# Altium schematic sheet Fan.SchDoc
size A4; SheetNumber: 9; SheetTotal: 16
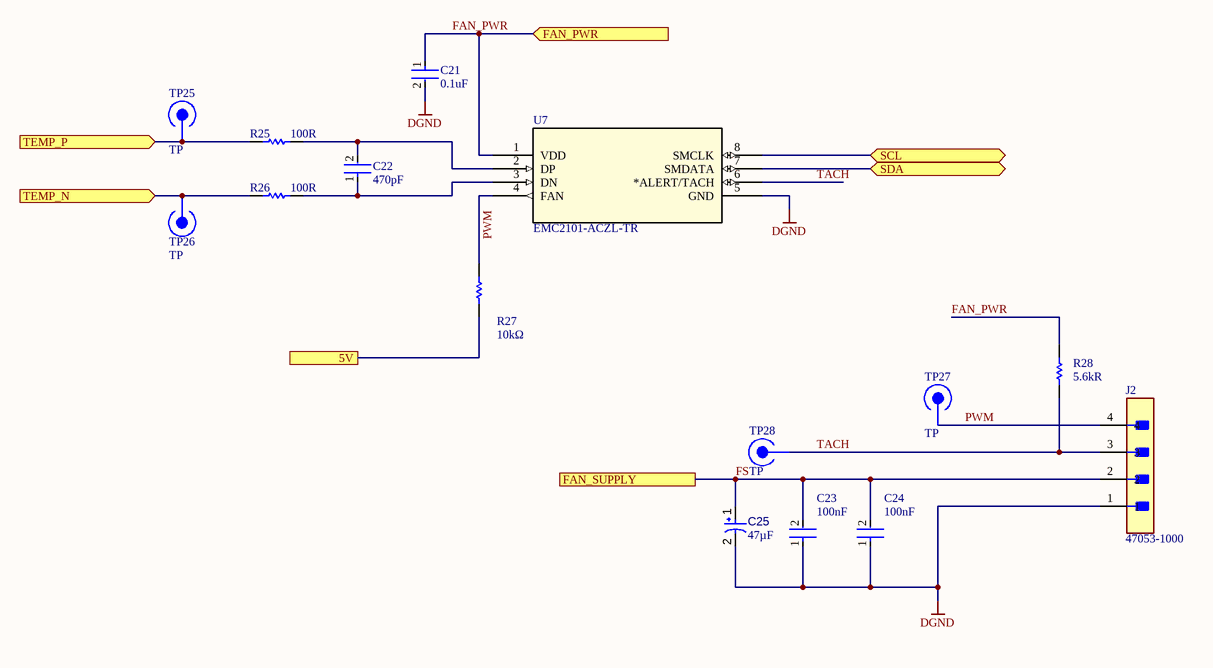
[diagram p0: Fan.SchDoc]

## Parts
C21  value 0.1uF  [FP-CC0402-IPC_C]  (hidden comment: CC0402KRX7R7BB104)
C22  value 470pF  [FP-0402-L_1_0_1-W_0_5_0_1-IPC_C]  (hidden comment: C0402C471K5RACTU)
C23  value 100nF  [FP-CC0402-IPC_B]  (hidden comment: CC0402KRX7R9BB104)
C24  value 100nF  [FP-CC0402-IPC_B]  (hidden comment: CC0402KRX7R9BB104)
C25  value 47µF  [VISH-7343-31_N]  (hidden comment: 293D476X9016D2TE3)
J2  47053-1000  [FP-470531000-MFG]
R25  value 100R  [RESC1005X40X25LL10T10]  (hidden comment: RK73H1ETTP1000F)
R26  value 100R  [RESC1005X40X25LL10T10]  (hidden comment: RK73H1ETTP1000F)
R27  value 10kΩ  [RESC1005X40X25LL10T10]  (hidden comment: RK73B1ETTP103J)
R28  value 5.6kR  [RESC1005X40X25LL10T10]  (hidden comment: RK73H1ETTP5601F)
TP25  TP  [TP-Footprint-1]
TP26  TP  [TP-Footprint-1]
TP27  TP  [TP-Footprint-1]
TP28  TP  [TP-Footprint-1]
U7  EMC2101-ACZL-TR  [EMC2101-ACZL-TR-Footprint-1]

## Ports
5V, FAN_PWR (in), FAN_SUPPLY, SCL (bidir), SDA (bidir), TEMP_N (in), TEMP_P (in)

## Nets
DGND: C21.2 C23.1 C24.1 C25.2 J2.1 U7.5(GND)
5V: R27.2 ; port 5V
FAN_PWR: C21.1 R28.2 U7.1(VDD) ; port FAN_PWR
FS: C23.2 C24.2 C25.1 J2.2 ; port FAN_SUPPLY
PWM: J2.4 R27.1 TP27.1 U7.4(FAN)
SCL: U7.8(SMCLK) ; port SCL
SDA: U7.7(SMDATA) ; port SDA
TACH: J2.3 R28.1 TP28.1 U7.6(*ALERT/TACH)
TEMP_N: R26.1 TP26.1 ; port TEMP_N
TEMP_P: R25.1 TP25.1 ; port TEMP_P
NetC22_1: C22.1 R26.2 U7.3(DN)
NetC22_2: C22.2 R25.2 U7.2(DP)

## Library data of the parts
C21 = CMP-001-00094-1: Multilayer Ceramic Capacitor, 0.1 uF, 25 V, ± 10%, X7R, 0402 [1005 Metric]; Rating: 16V; Reel Size: 8mm; Vendor: TTI
C22 = CMP-001-00097-1: CAPACITOR - Ceramic Chip Cap, 0402, 470 pf, 10%, 50V, X7R; Reel Size: 8mm; Vendor: TTI
C23 C24 = CMP-x00152-1: Ceramic Capacitor, Multilayer, Ceramic, 50V, 10% +Tol, 10% -Tol, X7R, 15% TC, 0.1uF, Surface Mount, 0402
C25 = CMP-001-00022-7: Solid Tantalum Chip Capacitor, 47 uF, +/- 10%, 16 V, -55 to 125 degC, 2917 (7343 Metric), RoHS, Tape and Reel; Manufacturer: Vishay Semiconductor; Voltage Rating: 16V
J2 = CMP-04776-000290-2: CONN HEADER VERT 4POS 2.54MM; NexarPartId: 854935; Manufacturer Lifecycle Status: ACTIVE; Voltage Rating (DC): 250V; Gender: Male; Plating: Copper; Number of Positions: 4; Glow Wire Compliant: Non-compliant; Current Rating: 500mA
R25 R26 = CMP-x00174-1: Fixed Resistor, Metal Glaze/thick Film, 0.1W, 100ohm, 75V, 1% +/-Tol, 100ppm/Cel, Surface Mount, 0402
R27 = CMP-009-00227-1: Fixed Resistor, Metal Glaze/thick Film, 0.1W, 10000ohm, 75V, 5% +/-Tol, 200ppm/Cel, Surface Mount, 0402; Rating: 1/10W; Vendor: TTI
R28 = CMP-x00164-1: Fixed Resistor, Metal Glaze/thick Film, 0.1W, 5600ohm, 75V, 1% +/-Tol, 100ppm/Cel, Surface Mount, 0402
TP25-TP28 = CMP-001-0086-3: digital shovel test point
U7 = CMP-x00137-1: Serial Switch/Digital Sensor, 11 Bit(s), 2Cel, Square, Surface Mount; Manufacturer: Microchip; Reel Width: 8mm; Template: MC_TSSOP_8; Vendor: Mouser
